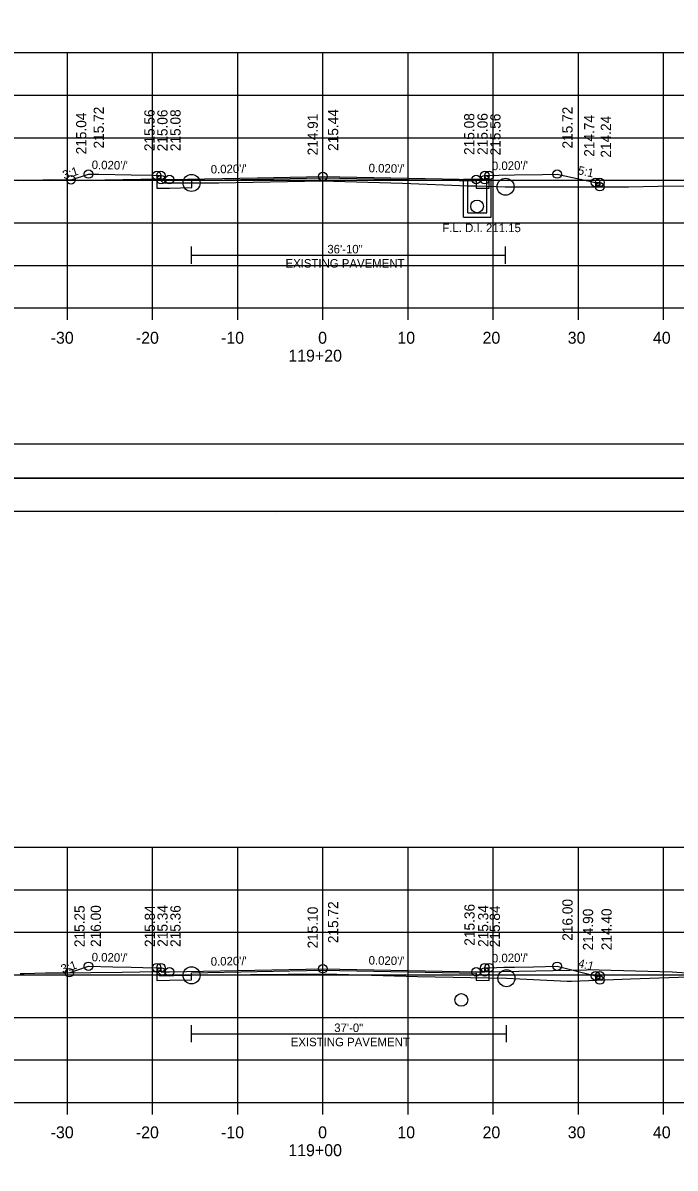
# Model space of a CAD drawing. Extents: x 1368968 to 1369915, y 377395 to 380381.
# Drawn here: x 1369716.6 to 1369793.1, y 379660.4 to 379794.9 of the extents above; entities that cross this region are included whole.
import ezdxf

# ---------------------------------------------------------------- set-up
doc = ezdxf.new("R2010")
doc.units = 0
for name, color, linetype in [('Default', 7, 'Continuous'), ('S_BORDER_NO_PLOT', 7, 'Continuous'), ('S_BREAKLINE_ANNOT', 7, 'Continuous'), ('S_BRIDGE', 7, 'Continuous'), ('S_BRIDGE_ANNOT', 7, 'Continuous'), ('S_CROSS_DRAIN', 7, 'Continuous'), ('S_CTL_TABLE', 7, 'Continuous'), ('S_CURB_ANNOT', 7, 'Continuous'), ('S_DITCHLINE_ANNOT', 7, 'Continuous'), ('S_DROP_INLET', 7, 'Continuous'), ('S_EXIST_ROW_ANNOT', 7, 'Continuous'), ('S_EXISTING_ALIGNMENT_ANNOT', 7, 'Continuous'), ('S_FENCE', 7, 'Continuous')]:
    doc.layers.add(name, color=color, linetype=linetype)

msp = doc.modelspace()

# ---------------------------------------------------------------- linework, layer by layer
at = {"layer": 'Default'}
for p, q in [((1369768.28, 379772.05), (1369768.28, 379775.75)), ((1369768.78, 379772.55), (1369768.78, 379775.75)), ((1369769.78, 379776.31), (1369769.78, 379775.48)), ((1369771.03, 379772.55), (1369771.03, 379775.7)), ((1369771.53, 379772.05), (1369771.53, 379775.68)), ((1369784.29, 379776.13), (1369784.29, 379775.63)), ((1369768.28, 379772.05), (1369771.53, 379772.05)), ((1369768.78, 379772.55), (1369771.03, 379772.55)), ((1369769.78, 379683.25), (1369769.78, 379682.42)), ((1369784.29, 379682.95), (1369784.29, 379682.45))]:
    msp.add_line(p, q, dxfattribs=at)
for centre in [(1369769.88, 379773.32), (1369768.03, 379680.11)]:
    msp.add_circle(centre, 0.75, dxfattribs=at)
at = {"layer": 'S_BORDER_NO_PLOT'}
for points in [[(1369732.27, 379776.96), (1369732.28, 379775.45), (1369733.78, 379775.48), (1369736.38, 379775.53), (1369736.38, 379776.36), (1369751.78, 379776.67), (1369769.78, 379776.31), (1369769.78, 379775.48), (1369771.28, 379775.45), (1369771.29, 379776.96)], [(1369732.27, 379683.9), (1369732.28, 379682.39), (1369733.78, 379682.42), (1369736.36, 379682.47), (1369736.36, 379683.3), (1369751.78, 379683.61), (1369769.78, 379683.25), (1369769.78, 379682.42), (1369771.28, 379682.39), (1369771.29, 379683.9)]]:
    msp.add_lwpolyline(points, dxfattribs=at)
at = {"layer": 'S_BREAKLINE_ANNOT'}
for p, q in [((1369611.78, 379761.39), (1369891.78, 379761.39)), ((1369721.78, 379759.99), (1369721.78, 379761.39)), ((1369731.78, 379759.99), (1369731.78, 379761.39)), ((1369741.78, 379759.99), (1369741.78, 379761.39)), ((1369751.78, 379759.99), (1369751.78, 379761.39)), ((1369761.78, 379759.99), (1369761.78, 379761.39)), ((1369771.78, 379759.99), (1369771.78, 379761.39)), ((1369781.78, 379759.99), (1369781.78, 379761.39)), ((1369791.78, 379759.99), (1369791.78, 379761.39)), ((1369611.78, 379668.06), (1369891.78, 379668.06)), ((1369721.78, 379666.66), (1369721.78, 379668.06)), ((1369731.78, 379666.66), (1369731.78, 379668.06)), ((1369741.78, 379666.66), (1369741.78, 379668.06)), ((1369751.78, 379666.66), (1369751.78, 379668.06)), ((1369761.78, 379666.66), (1369761.78, 379668.06)), ((1369771.78, 379666.66), (1369771.78, 379668.06)), ((1369781.78, 379666.66), (1369781.78, 379668.06)), ((1369791.78, 379666.66), (1369791.78, 379668.06))]:
    msp.add_line(p, q, dxfattribs=at)
at = {"layer": 'S_BRIDGE_ANNOT'}
for p, q in [((1369909.96, 379745.39), (1369593.78, 379745.39)), ((1369593.78, 379737.52), (1369909.96, 379737.52)), ((1369746.3, 379737.26), (1369746.3, 379737.26)), ((1369746.3, 379737.26), (1369746.3, 379737.26))]:
    msp.add_line(p, q, dxfattribs=at)
at = {"layer": 'S_CROSS_DRAIN'}
for p, q in [((1369736.36, 379767.59), (1369773.22, 379767.59)), ((1369770.78, 379683.4), (1369782.77, 379683.64)), ((1369792.77, 379683.38), (1369782.77, 379683.64)), ((1369798.19, 379682.99), (1369792.77, 379683.38)), ((1369736.36, 379676.13), (1369773.33, 379676.13))]:
    msp.add_line(p, q, dxfattribs=at)
at = {"layer": 'S_CTL_TABLE'}
for points in [[(1369716.05, 379776.35), (1369718.91, 379776.44), (1369719.64, 379776.47), (1369722.63, 379776.43), (1369724.46, 379776.4), (1369726.2, 379776.43), (1369732.53, 379776.54), (1369732.94, 379776.18), (1369733.03, 379776.1), (1369735.81, 379776.07), (1369736.36, 379776.07), (1369737.16, 379776.07), (1369739.56, 379776.1), (1369751.64, 379776.31), (1369761.11, 379776.03), (1369768.82, 379775.75), (1369769.9, 379775.75), (1369770.97, 379775.7), (1369773.19, 379775.63), (1369773.22, 379775.63), (1369773.23, 379775.63), (1369773.24, 379775.63), (1369778.97, 379775.63), (1369787.67, 379775.63), (1369791.14, 379775.69), (1369796.28, 379775.75)], [(1369716.24, 379683.2), (1369716.7, 379683.21), (1369719.21, 379683.29), (1369721.84, 379683.31), (1369724.53, 379683.35), (1369728.23, 379683.39), (1369732.35, 379683.44), (1369732.55, 379683.26), (1369732.87, 379682.99), (1369734.29, 379682.99), (1369736.36, 379683), (1369743.28, 379683.09), (1369752.08, 379683.16), (1369762.89, 379682.88), (1369773.33, 379682.66), (1369780.46, 379682.31), (1369780.6, 379682.3), (1369780.97, 379682.32), (1369787.88, 379682.6), (1369794.66, 379682.83)]]:
    msp.add_lwpolyline(points, dxfattribs=at)
at = {"layer": 'S_CURB_ANNOT'}
for points in [[(1369722.21, 379776.43), (1369722.21, 379776.44), (1369724.27, 379777.12), (1369725.49, 379777.09), (1369729.27, 379777.02), (1369731.72, 379776.97), (1369732.27, 379776.96), (1369732.34, 379776.96), (1369732.77, 379776.96), (1369732.77, 379776.7), (1369732.78, 379776.46), (1369732.78, 379776.46), (1369733.78, 379776.48), (1369733.81, 379776.48), (1369744.1, 379776.69), (1369751.78, 379776.84), (1369751.78, 379776.84), (1369769.78, 379776.48), (1369770.78, 379776.46), (1369770.79, 379776.96), (1369771.07, 379776.96), (1369771.29, 379776.96), (1369771.29, 379776.96), (1369772.43, 379776.98), (1369774.29, 379777.02), (1369777.54, 379777.08), (1369779.29, 379777.12), (1369779.29, 379777.12), (1369783.79, 379776.13), (1369784.29, 379776.13), (1369784.29, 379775.63)], [(1369722.01, 379683.31), (1369722.78, 379683.56), (1369724.27, 379684.06), (1369727.13, 379684), (1369729.27, 379683.96), (1369730.65, 379683.93), (1369732.27, 379683.9), (1369732.49, 379683.9), (1369732.77, 379683.9), (1369732.77, 379683.73), (1369732.78, 379683.4), (1369733.32, 379683.41), (1369733.78, 379683.42), (1369733.78, 379683.42), (1369751.78, 379683.78), (1369751.78, 379683.78), (1369769.78, 379683.42), (1369770.17, 379683.41), (1369770.78, 379683.4), (1369770.78, 379683.56), (1369770.79, 379683.9), (1369770.95, 379683.9), (1369771.29, 379683.9), (1369773.03, 379683.94), (1369774.29, 379683.96), (1369776.49, 379684), (1369779.29, 379684.06), (1369783.79, 379682.95), (1369783.79, 379682.95), (1369784.29, 379682.95), (1369784.29, 379682.45)]]:
    msp.add_lwpolyline(points, dxfattribs=at)
at = {"layer": 'S_DITCHLINE_ANNOT'}
for p, q in [((1369611.78, 379791.39), (1369891.78, 379791.39)), ((1369721.78, 379761.39), (1369721.78, 379791.39)), ((1369731.78, 379761.39), (1369731.78, 379791.39)), ((1369741.78, 379761.39), (1369741.78, 379791.39)), ((1369751.78, 379761.39), (1369751.78, 379791.39)), ((1369761.78, 379761.39), (1369761.78, 379791.39)), ((1369771.78, 379761.39), (1369771.78, 379791.39)), ((1369781.78, 379761.39), (1369781.78, 379791.39)), ((1369791.78, 379761.39), (1369791.78, 379791.39)), ((1369611.78, 379786.39), (1369891.78, 379786.39)), ((1369611.78, 379781.39), (1369891.78, 379781.39)), ((1369611.78, 379776.39), (1369891.78, 379776.39)), ((1369611.78, 379771.39), (1369891.78, 379771.39)), ((1369611.78, 379766.39), (1369891.78, 379766.39)), ((1369611.78, 379761.39), (1369891.78, 379761.39)), ((1369611.78, 379698.06), (1369891.78, 379698.06)), ((1369721.78, 379668.06), (1369721.78, 379698.06)), ((1369731.78, 379668.06), (1369731.78, 379698.06)), ((1369741.78, 379668.06), (1369741.78, 379698.06)), ((1369751.78, 379668.06), (1369751.78, 379698.06)), ((1369761.78, 379668.06), (1369761.78, 379698.06)), ((1369771.78, 379668.06), (1369771.78, 379698.06)), ((1369781.78, 379668.06), (1369781.78, 379698.06)), ((1369791.78, 379668.06), (1369791.78, 379698.06)), ((1369611.78, 379693.06), (1369891.78, 379693.06)), ((1369611.78, 379688.06), (1369891.78, 379688.06)), ((1369611.78, 379683.06), (1369891.78, 379683.06)), ((1369611.78, 379678.06), (1369891.78, 379678.06)), ((1369611.78, 379673.06), (1369891.78, 379673.06)), ((1369611.78, 379668.06), (1369891.78, 379668.06))]:
    msp.add_line(p, q, dxfattribs=at)
at = {"layer": 'S_DROP_INLET'}
for p, q in [((1369581.38, 379741.42), (1369914.71, 379741.42)), ((1369581.38, 379741.41), (1369914.71, 379741.41))]:
    msp.add_line(p, q, dxfattribs=at)
for points in [[(1369581.37, 379954.75), (1369914.71, 379954.75), (1369914.71, 379741.41), (1369581.37, 379741.41)], [(1369827.7, 379950.85), (1369827.7, 379940.97), (1369863.43, 379940.97), (1369863.43, 379938.05), (1369886.63, 379938.05), (1369886.63, 379913.72), (1369909.96, 379913.72), (1369909.96, 379745.39), (1369593.78, 379745.39), (1369593.78, 379950.85)], [(1369581.37, 379741.41), (1369914.71, 379741.41), (1369914.71, 379528.07), (1369581.37, 379528.07)], [(1369827.7, 379737.52), (1369827.7, 379727.64), (1369863.43, 379727.64), (1369863.43, 379724.72), (1369886.63, 379724.72), (1369886.63, 379700.38), (1369909.96, 379700.38), (1369909.96, 379532.06), (1369593.78, 379532.06), (1369593.78, 379737.52)]]:
    msp.add_lwpolyline(points, close=True, dxfattribs=at)
for centre, radius in [((1369722.21, 379776.43), 0.5), ((1369724.27, 379777.12), 0.5), ((1369732.27, 379776.96), 0.5), ((1369732.77, 379776.96), 0.5), ((1369732.78, 379776.46), 0.5), ((1369733.78, 379776.48), 0.5), ((1369733.78, 379776.48), 0.5), ((1369736.36, 379776.07), 1), ((1369751.78, 379776.84), 0.5), ((1369769.78, 379776.48), 0.5), ((1369769.78, 379776.48), 0.5), ((1369770.78, 379776.46), 0.5), ((1369770.79, 379776.96), 0.5), ((1369771.29, 379776.96), 0.5), ((1369779.29, 379777.12), 0.5), ((1369773.22, 379775.63), 1), ((1369783.79, 379776.13), 0.5), ((1369784.29, 379776.13), 0.5), ((1369784.29, 379775.63), 0.5), ((1369724.27, 379684.06), 0.5), ((1369732.27, 379683.9), 0.5), ((1369732.77, 379683.9), 0.5), ((1369736.36, 379683), 1), ((1369751.78, 379683.78), 0.5), ((1369770.79, 379683.9), 0.5), ((1369771.29, 379683.9), 0.5), ((1369779.29, 379684.06), 0.5), ((1369722.01, 379683.31), 0.5), ((1369732.78, 379683.4), 0.5), ((1369733.78, 379683.42), 0.5), ((1369733.78, 379683.42), 0.5), ((1369769.78, 379683.42), 0.5), ((1369769.78, 379683.42), 0.5), ((1369770.78, 379683.4), 0.5), ((1369773.33, 379682.66), 1), ((1369783.79, 379682.95), 0.5), ((1369784.29, 379682.95), 0.5), ((1369784.29, 379682.45), 0.5)]:
    msp.add_circle(centre, radius, dxfattribs=at)
at = {"layer": 'S_EXIST_ROW_ANNOT'}
for p, q in [((1369768.28, 379775.75), (1369768.28, 379776.48)), ((1369771.53, 379776.48), (1369768.28, 379776.48)), ((1369768.78, 379775.75), (1369768.78, 379776.48)), ((1369771.03, 379775.7), (1369771.03, 379776.48)), ((1369771.53, 379775.69), (1369771.53, 379776.48)), ((1369736.36, 379766.59), (1369736.36, 379768.59)), ((1369773.22, 379766.59), (1369773.22, 379768.59)), ((1369736.36, 379675.13), (1369736.36, 379677.13)), ((1369773.33, 379675.13), (1369773.33, 379677.13))]:
    msp.add_line(p, q, dxfattribs=at)
at = {"layer": 'S_EXISTING_ALIGNMENT_ANNOT'}
for p, q in [((1369751.78, 379776.31), (1369751.78, 379786.31)), ((1369751.78, 379683.16), (1369751.78, 379693.16))]:
    msp.add_line(p, q, dxfattribs=at)

# ---------------------------------------------------------------- texts
at = {"layer": 'S_BRIDGE'}
for s, p in [('-30', (1369719.82, 379757.19)), ('-20', (1369729.82, 379757.19)), ('-10', (1369739.82, 379757.19)), ('0', (1369751.22, 379757.19)), ('10', (1369760.52, 379757.19)), ('20', (1369770.52, 379757.19)), ('30', (1369780.52, 379757.19)), ('40', (1369790.52, 379757.19)), ('119+20', (1369747.72, 379755.09)), ('-30', (1369719.82, 379663.86)), ('-20', (1369729.82, 379663.86)), ('-10', (1369739.82, 379663.86)), ('0', (1369751.22, 379663.86)), ('10', (1369760.52, 379663.86)), ('20', (1369770.52, 379663.86)), ('30', (1369780.52, 379663.86)), ('40', (1369790.52, 379663.86)), ('119+00', (1369747.72, 379661.76))]:
    msp.add_text(s, height=1.4, dxfattribs=at).set_placement(p)
at = {"layer": 'S_EXIST_ROW_ANNOT'}
for s, p in [('F.L. D.I. 211.15', (1369765.8, 379770.3)), ('36\'-10"', (1369752.3, 379767.8)), ('EXISTING PAVEMENT', (1369747.39, 379766.13)), ('37\'-0"', (1369753.11, 379676.34)), ('EXISTING PAVEMENT', (1369748.01, 379674.67))]:
    msp.add_text(s, height=1, dxfattribs=at).set_placement(p)
at = {"layer": 'S_EXISTING_ALIGNMENT_ANNOT'}
for s, p in [('215.72', (1369726.07, 379780.12)), ('215.72', (1369781.09, 379780.12)), ('215.04', (1369724.01, 379779.43)), ('215.56', (1369732.02, 379779.81)), ('215.06', (1369733.54, 379779.79)), ('215.08', (1369735.07, 379779.81)), ('214.91', (1369751.18, 379779.31)), ('215.44', (1369753.58, 379779.84)), ('215.08', (1369769.56, 379779.36)), ('215.06', (1369771.12, 379779.37)), ('215.56', (1369772.63, 379779.31)), ('214.74', (1369783.65, 379779.15)), ('214.24', (1369785.6, 379779.05)), ('215.25', (1369723.81, 379686.31)), ('216.00', (1369725.72, 379686.33)), ('215.84', (1369732.06, 379686.32)), ('215.34', (1369733.56, 379686.35)), ('215.36', (1369735.07, 379686.33)), ('215.10', (1369751.18, 379686.16)), ('215.72', (1369753.58, 379686.78)), ('215.36', (1369769.59, 379686.48)), ('215.34', (1369771.2, 379686.34)), ('215.84', (1369772.56, 379686.3)), ('216.00', (1369781.09, 379687.06)), ('214.90', (1369783.5, 379685.92)), ('214.40', (1369785.68, 379685.95))]:
    msp.add_text(s, height=1.2, rotation=90, dxfattribs=at).set_placement(p)
at = {"layer": 'S_FENCE'}
for s, rotation, p in [("0.020'/'", 358.8542, (1369724.63, 379777.71)), ("0.020'/'", 1.1457, (1369738.62, 379777.18)), ("0.020'/'", 358.8543, (1369757.14, 379777.33)), ("0.020'/'", 1.1458, (1369771.63, 379777.57)), ('3:1', 18.412, (1369721.4, 379776.48)), ('5:1', 347.6185, (1369781.64, 379777.11)), ("0.020'/'", 358.8542, (1369724.63, 379684.65)), ("0.020'/'", 1.1458, (1369771.63, 379684.51)), ('3:1', 18.4288, (1369721.22, 379683.23)), ("0.020'/'", 1.1457, (1369738.62, 379684.12)), ("0.020'/'", 358.8543, (1369757.14, 379684.27)), ('4:1', 346.1786, (1369781.66, 379683.99))]:
    msp.add_text(s, height=1, rotation=rotation, dxfattribs=at).set_placement(p)

doc.saveas('drawing.dxf')
